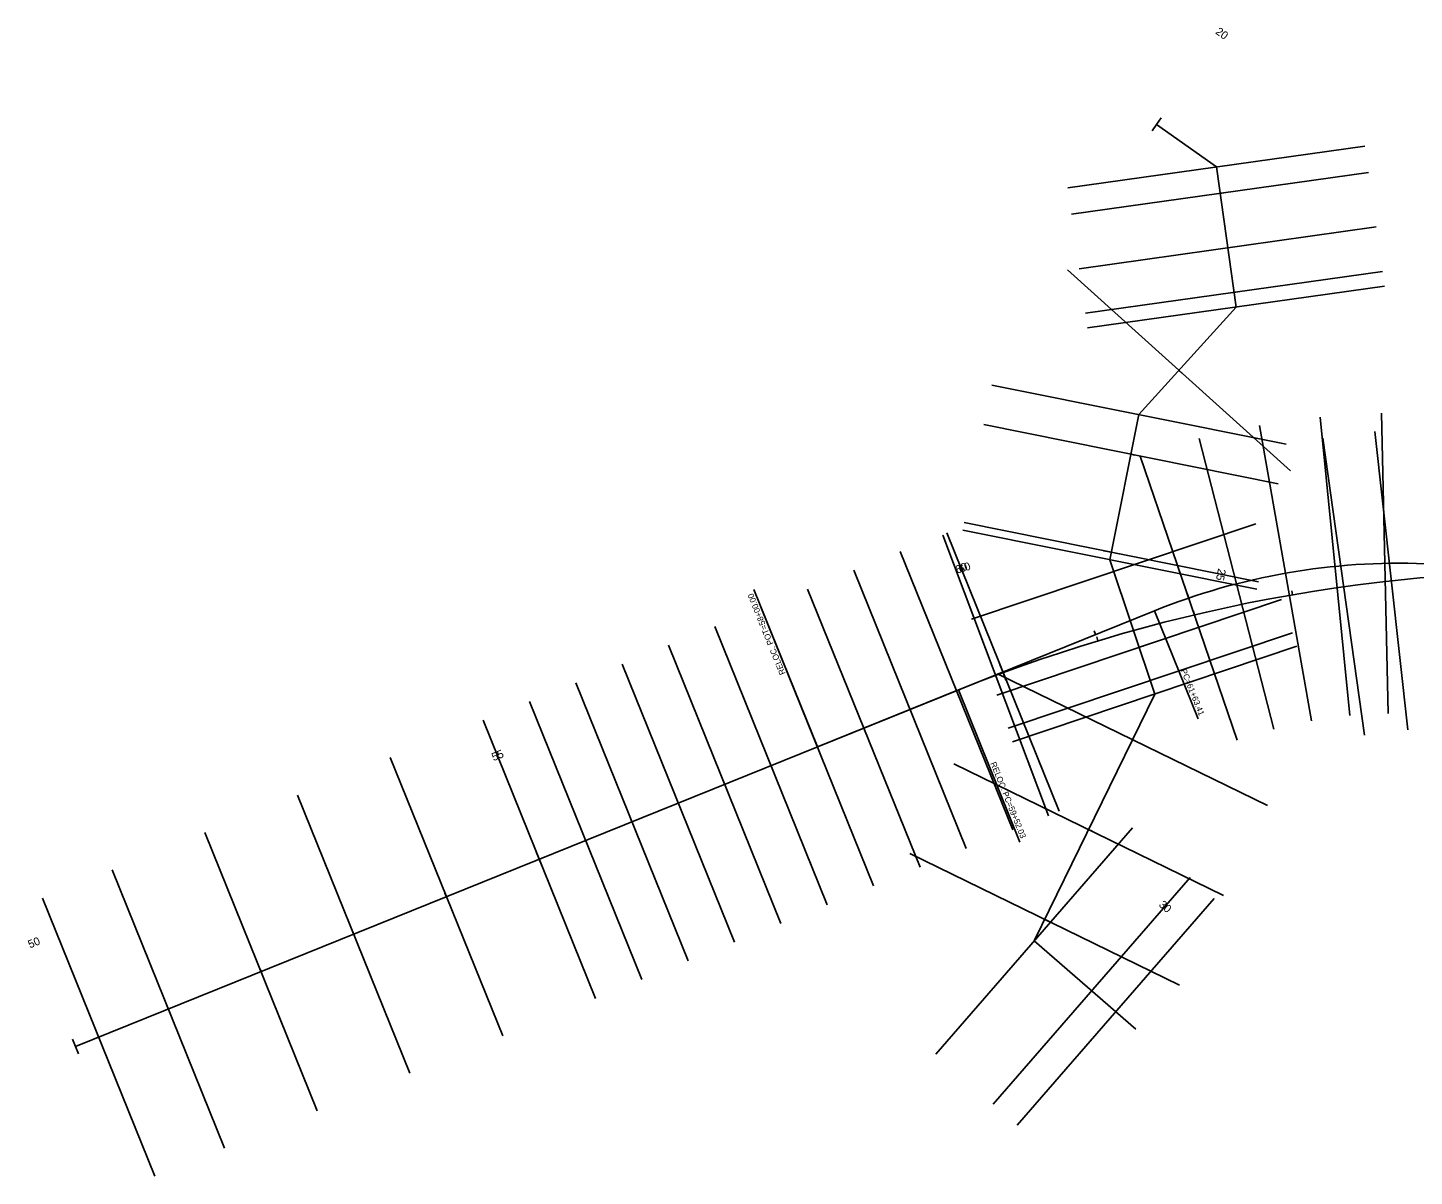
# Model space of a CAD drawing. Extents: x 1966723 to 1969285, y 1117318 to 1118467.
# Drawn here: x 1966723 to 1968109, y 1117318 to 1118467 of the extents above; entities that cross this region are included whole.
import ezdxf

# ---------------------------------------------------------------- set-up
doc = ezdxf.new("R2010")
doc.units = 0
for name, color, linetype in [('Level 1', 7, 'Continuous'), ('Level 19', 7, 'Continuous'), ('Level 21', 7, 'Continuous'), ('Level 39', 7, 'Continuous'), ('Level 50', 7, 'Continuous'), ('Level 51', 7, 'Continuous')]:
    doc.layers.add(name, color=color, linetype=linetype)

msp = doc.modelspace()

# ---------------------------------------------------------------- linework, layer by layer
at = {"layer": 'Level 1'}
for p, q in [((1967851.7, 1118370.2), (1967856.4, 1118376.7)), ((1967851.7, 1118370.2), (1967847.1, 1118363.7)), ((1967851.7, 1118370.2), (1967911.4, 1118327.7)), ((1967911.4, 1118327.7), (1967931.1, 1118187.5)), ((1967915.1, 1118301.2), (1967919, 1118301.7)), ((1967929, 1118202.2), (1967933, 1118202.7)), ((1967931.1, 1118187.5), (1967834, 1118080)), ((1967874, 1118124.2), (1967876.9, 1118121.6)), ((1967834, 1118080), (1967804.8, 1117934.9)), ((1967826.1, 1118040.4), (1967830, 1118039.6)), ((1967806.3, 1117942.4), (1967798.5, 1117943.9)), ((1967804.8, 1117934.9), (1967849.8, 1117800.6)), ((1967806.3, 1117942.4), (1967814.2, 1117940.8)), ((1968079.9, 1117931.3), (1968079.8, 1117935.3)), ((1967980.5, 1117921.5), (1967979.8, 1117925.4)), ((1967883.8, 1117896.6), (1967882.5, 1117900.4)), ((1966770.7, 1117448.1), (1967849.5, 1117883.9)), ((1967849.5, 1117883.9), (1967893.1, 1117775.9)), ((1967790.7, 1117860.1), (1967789.2, 1117863.8)), ((1967834.2, 1117847.3), (1967838, 1117848.6)), ((1967698, 1117822.7), (1967695, 1117830.1)), ((1967698, 1117822.7), (1967700.9, 1117815.2)), ((1967849.8, 1117800.6), (1967729.3, 1117553.7)), ((1967605.2, 1117785.2), (1967603.7, 1117788.9)), ((1967512.5, 1117747.7), (1967511, 1117751.5)), ((1967827.6, 1117755), (1967831.1, 1117753.2)), ((1967419.8, 1117710.3), (1967418.3, 1117714)), ((1967327.1, 1117672.8), (1967325.6, 1117676.5)), ((1967783.7, 1117665.1), (1967787.3, 1117663.4)), ((1967234.3, 1117635.4), (1967231.3, 1117642.8)), ((1967234.3, 1117635.4), (1967237.3, 1117628)), ((1967141.6, 1117597.9), (1967140.1, 1117601.6)), ((1967739.8, 1117575.2), (1967743.4, 1117573.5)), ((1967048.9, 1117560.5), (1967047.4, 1117564.2)), ((1967729.3, 1117553.7), (1967830.8, 1117465.4)), ((1966956.2, 1117523), (1966954.7, 1117526.7)), ((1967786.6, 1117503.8), (1967781.4, 1117497.8)), ((1967786.6, 1117503.8), (1967791.9, 1117509.8)), ((1966863.5, 1117485.6), (1966862, 1117489.3)), ((1966770.7, 1117448.1), (1966767.7, 1117455.5)), ((1966770.7, 1117448.1), (1966773.7, 1117440.7))]:
    msp.add_line(p, q, dxfattribs=at)
msp.add_arc((1968094.4, 1117277.5), 653.9, 87.7266, 111.9958, dxfattribs=at)
at = {"layer": 'Level 19'}
for p, q in [((1968086.5, 1117913.9), (1968086, 1117917.9)), ((1967987.5, 1117899.9), (1967986.8, 1117903.8)), ((1967889.5, 1117879.8), (1967888.6, 1117883.7)), ((1967793, 1117853.8), (1967791.8, 1117857.7)), ((1967698.2, 1117822), (1967695.4, 1117829.5)), ((1967698.2, 1117822), (1967701, 1117814.5)), ((1967512.5, 1117747.7), (1967653.5, 1117804.7)), ((1967605.2, 1117785.2), (1967603.7, 1117788.9)), ((1967512.5, 1117747.7), (1967511, 1117751.5))]:
    msp.add_line(p, q, dxfattribs=at)
msp.add_arc((1968266.6, 1116286.8), 1637, 87.7266, 111.9958, dxfattribs=at)
at = {"layer": 'Level 39'}
for p, q in [((1967512.5, 1117747.7), (1967449, 1117905)), ((1967653.5, 1117804.7), (1967714.9, 1117652.6))]:
    msp.add_line(p, q, dxfattribs=at)
at = {"layer": 'Level 50'}
for p, q in [((1968059.9, 1118348.5), (1967762.8, 1118306.8)), ((1968063.6, 1118322.1), (1967766.5, 1118280.3)), ((1968071.3, 1118267.6), (1967774.2, 1118225.9)), ((1967985.4, 1118023.8), (1967762.6, 1118224.7)), ((1968077.5, 1118223), (1967780.5, 1118181.3)), ((1968079.6, 1118208.4), (1967782.5, 1118166.7)), ((1967981.1, 1118050.3), (1967687, 1118109.6)), ((1967973.1, 1118010.8), (1967679, 1118070)), ((1968015.3, 1118077.6), (1968044.8, 1117779)), ((1968076.6, 1118081.3), (1968083.3, 1117781.3)), ((1967894.3, 1118056.2), (1967969, 1117765.6)), ((1967954.4, 1118069.2), (1968006.6, 1117773.8)), ((1967835.4, 1118038.6), (1967932.1, 1117754.6)), ((1967641.8, 1117961.7), (1967754.1, 1117683.6)), ((1967951.9, 1117905.3), (1967657.8, 1117964.5)), ((1967953.4, 1117912.7), (1967659.3, 1117972)), ((1967951, 1117970.8), (1967666.5, 1117875.5)), ((1967549, 1117924.3), (1967661.4, 1117646.1)), ((1967976.4, 1117895), (1967691.9, 1117799.6)), ((1967456.3, 1117886.8), (1967568.7, 1117608.7)), ((1967987.5, 1117861.8), (1967703.1, 1117766.4)), ((1967363.6, 1117849.4), (1967476, 1117571.2)), ((1967992, 1117848.3), (1967707.6, 1117752.9)), ((1967962.4, 1117689.2), (1967692.7, 1117820.8)), ((1967270.9, 1117811.9), (1967383.2, 1117533.8)), ((1967178.2, 1117774.5), (1967290.5, 1117496.3)), ((1967085.4, 1117737), (1967197.8, 1117458.9)), ((1967918.5, 1117599.3), (1967648.9, 1117730.9)), ((1966992.7, 1117699.6), (1967105.1, 1117421.4)), ((1966900, 1117662.1), (1967012.4, 1117383.9)), ((1967827.7, 1117666.9), (1967630.9, 1117440.4)), ((1967874.6, 1117509.5), (1967605, 1117641)), ((1966807.3, 1117624.7), (1966919.6, 1117346.5)), ((1967885.1, 1117617), (1967688.2, 1117390.6)), ((1966737.7, 1117596.6), (1966850.1, 1117318.4)), ((1967909.2, 1117596), (1967712.4, 1117369.6))]:
    msp.add_line(p, q, dxfattribs=at)
at = {"layer": 'Level 51'}
for p, q in [((1968018, 1118056.5), (1968059.7, 1117759.4)), ((1968070, 1118063), (1968103, 1117764.8)), ((1967637.9, 1117959.6), (1967743.5, 1117678.8)), ((1967595.4, 1117943), (1967707.8, 1117664.8)), ((1967549, 1117924.3), (1967661.4, 1117646.1)), ((1967502.7, 1117905.6), (1967615.1, 1117627.4)), ((1967456.3, 1117886.8), (1967568.7, 1117608.7)), ((1967410, 1117868.1), (1967522.3, 1117589.9)), ((1967363.6, 1117849.4), (1967476, 1117571.2)), ((1967317.2, 1117830.6), (1967429.6, 1117552.5)), ((1967270.9, 1117811.9), (1967383.2, 1117533.8)), ((1967224.5, 1117793.2), (1967336.9, 1117515)), ((1967178.2, 1117774.5), (1967290.5, 1117496.3))]:
    msp.add_line(p, q, dxfattribs=at)

# ---------------------------------------------------------------- texts
at = {"layer": 'Level 1'}
msp.add_text('PC=61+63.41', height=6, rotation=291.9958, dxfattribs=at).set_placement((1967875.7, 1117824.3))
at = {"layer": 'Level 19'}
msp.add_text('60', height=8, rotation=20.3169, dxfattribs=at).set_placement((1967655.4, 1117921.3))
at = {"layer": 'Level 21'}
for s, rotation, p in [('20', 324.4755, (1967909.9, 1118461.4)), ('60', 21.9958, (1967652.3, 1117920.7)), ('25', 258.6104, (1967913.3, 1117926.5)), ('55', 21.9958, (1967188.7, 1117733.4)), ('30', 318.9994, (1967853.3, 1117589)), ('50', 21.9958, (1966725.1, 1117546.2))]:
    msp.add_text(s, height=8, rotation=rotation, dxfattribs=at).set_placement(p)
at = {"layer": 'Level 39'}
for s, rotation, p in [('RELOC. POT=58+00.00', 111.9958, (1967480.7, 1117821.2)), ('RELOC. PC=59+52.03', 291.9958, (1967685.3, 1117731.3))]:
    msp.add_text(s, height=6, rotation=rotation, dxfattribs=at).set_placement(p)

doc.saveas('drawing.dxf')
